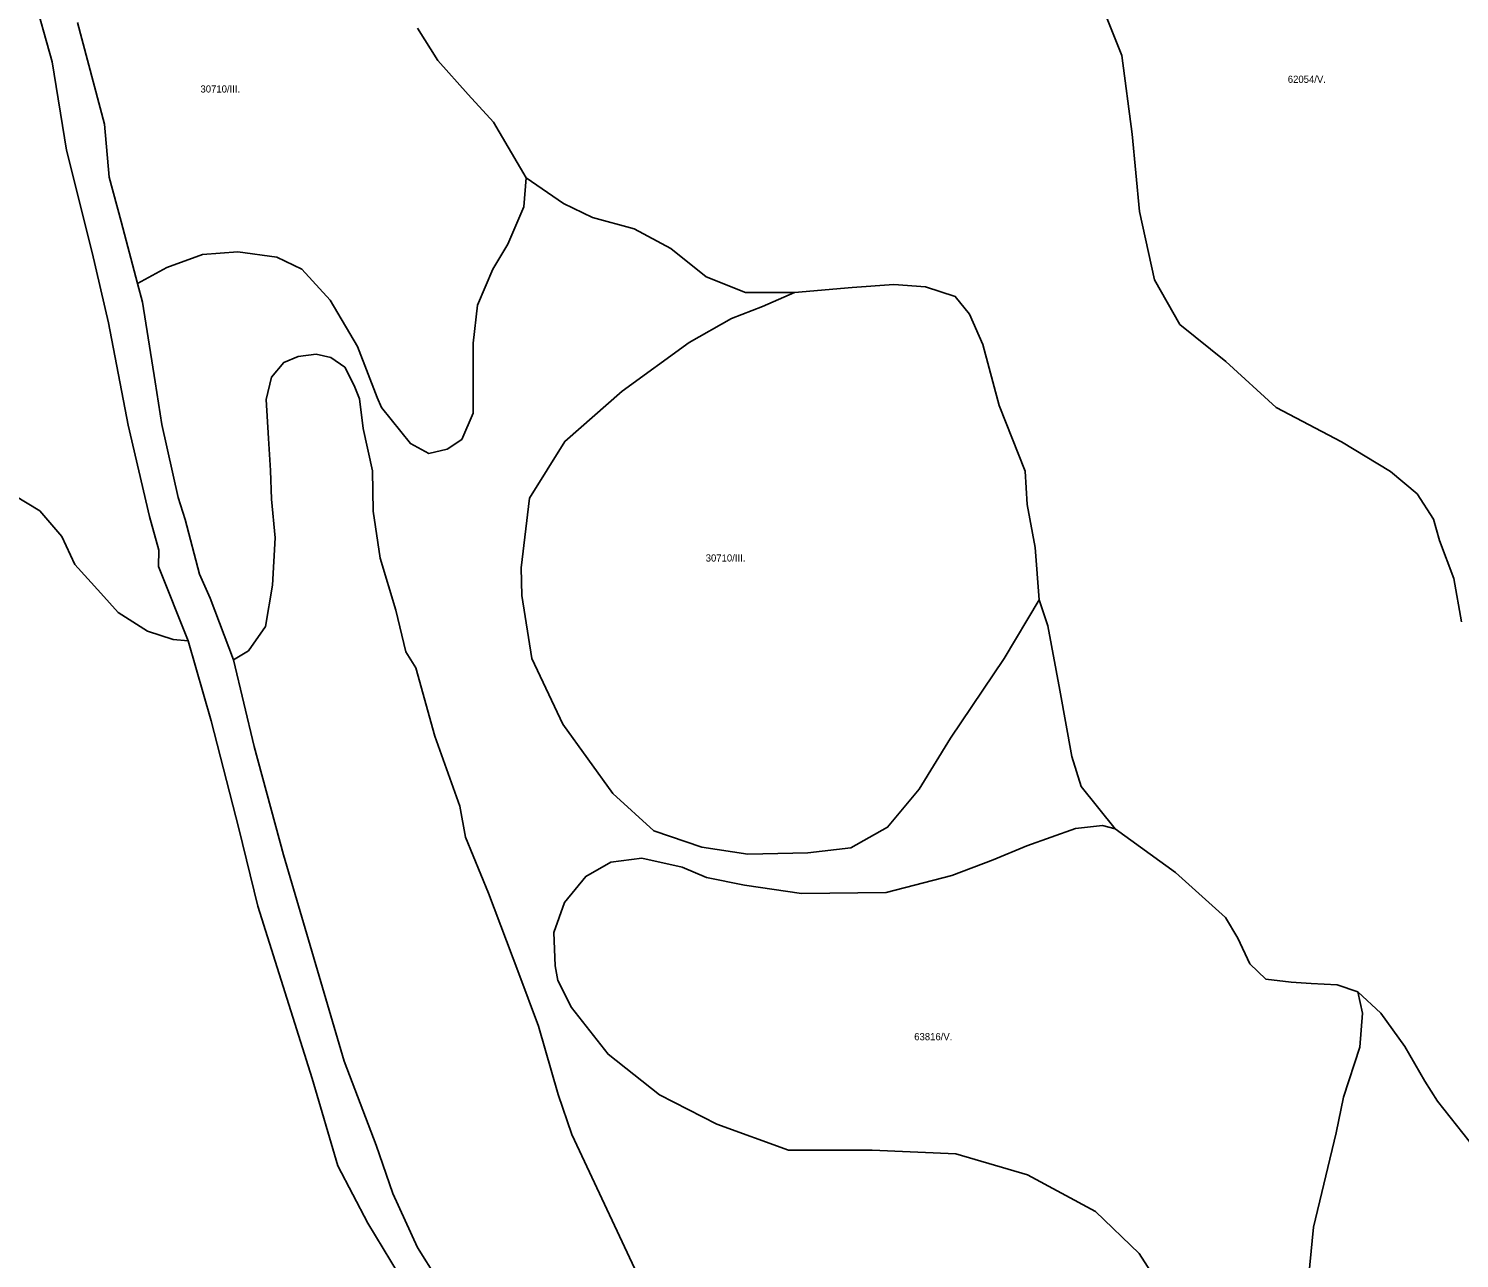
# Model space of a CAD drawing. Extents: x -521621 to -516761, y -1190184 to -1184927.
# Drawn here: x -519227 to -518423, y -1188783 to -1188092 of the extents above; entities that cross this region are included whole.
import ezdxf

# ---------------------------------------------------------------- set-up
doc = ezdxf.new("R2010")
doc.units = 0
doc.layers.add('BPEJ_s', color=7, linetype='Continuous')

msp = doc.modelspace()

# ---------------------------------------------------------------- linework, layer by layer
at = {"layer": 'BPEJ_s'}
for points in [[(-518422.16, -1188425.14), (-518426.52, -1188400.94), (-518434.45, -1188379.52), (-518437.78, -1188367.58), (-518446.95, -1188353.39), (-518461.97, -1188340.87), (-518489.49, -1188324.18), (-518526.18, -1188304.99), (-518554.54, -1188279.12), (-518580.39, -1188258.26), (-518594.57, -1188233.22), (-518602.91, -1188194.83), (-518607.08, -1188151.44), (-518612.92, -1188107.21), (-518629.6, -1188065.48)], [(-518629.6, -1188065.48), (-518612.92, -1188107.21), (-518607.08, -1188151.44), (-518602.91, -1188194.83), (-518594.57, -1188233.22), (-518580.39, -1188258.26), (-518554.54, -1188279.12), (-518526.18, -1188304.99), (-518489.49, -1188324.18), (-518461.97, -1188340.87), (-518446.95, -1188353.39), (-518437.78, -1188367.58), (-518434.45, -1188379.52), (-518426.52, -1188400.94), (-518422.16, -1188425.14)], [(-519224.72, -1188071.37), (-519213.76, -1188110.85), (-519205.61, -1188160.41), (-519191.21, -1188217.96), (-519182.06, -1188257.39), (-519170.92, -1188314.73), (-519158.98, -1188366.11), (-519153.68, -1188385.07), (-519153.92, -1188394.14), (-519137.31, -1188435.82), (-519145.71, -1188435.12), (-519160.09, -1188430.53), (-519176.55, -1188419.9), (-519186.35, -1188409.06), (-519200.93, -1188393), (-519208.23, -1188377.36), (-519220.53, -1188362.97), (-519234.9, -1188354.21)], [(-519014.92, -1188798.36), (-519036.31, -1188762.86), (-519053.26, -1188730.58), (-519067.71, -1188681.58), (-519098.18, -1188584.82), (-519108.75, -1188541.22), (-519124.4, -1188480.74), (-519137.31, -1188435.82), (-519153.92, -1188394.14), (-519153.68, -1188385.07), (-519158.98, -1188366.11), (-519170.92, -1188314.73), (-519182.06, -1188257.39), (-519191.21, -1188217.96), (-519205.61, -1188160.41), (-519213.76, -1188110.85), (-519224.72, -1188071.37)], [(-519008.55, -1188091.89), (-518997.05, -1188110.14), (-518980, -1188129.19), (-518965.73, -1188144.66), (-518947.49, -1188176), (-518948.68, -1188192.27), (-518957.8, -1188213.29), (-518966.12, -1188227.18), (-518974.85, -1188247.41), (-518977.23, -1188268.83), (-518977.23, -1188308.11), (-518983.57, -1188322.78), (-518991.9, -1188328.34), (-519002.2, -1188330.72), (-519012.51, -1188325.17), (-519023.22, -1188311.68), (-519028.77, -1188304.93), (-519031.1, -1188299.37), (-519042.15, -1188270.59), (-519057.57, -1188244.73), (-519073.4, -1188227.22), (-519087.58, -1188220.55), (-519109.46, -1188217.42), (-519129.25, -1188219.09), (-519149.26, -1188226.38), (-519165.74, -1188235.26), (-519174.9, -1188200.44), (-519181.72, -1188175.58), (-519184.34, -1188145.83), (-519199.49, -1188088.69)], [(-519199.49, -1188088.69), (-519184.34, -1188145.83), (-519181.72, -1188175.58), (-519174.9, -1188200.44), (-519165.74, -1188235.26), (-519162.96, -1188245.84), (-519155.8, -1188290.44), (-519152.02, -1188314.53), (-519142.86, -1188355.35), (-519138.89, -1188367.7), (-519130.84, -1188398.42), (-519124.86, -1188412.01), (-519111.79, -1188446.64), (-519100.17, -1188495.16), (-519083.81, -1188556.01), (-519049.7, -1188671.8), (-519031.72, -1188719.07), (-519022.31, -1188746.23), (-519008.42, -1188776.51), (-518997.38, -1188794.11)], [(-518417.8, -1188716.79), (-518435.53, -1188694.4), (-518442.78, -1188683.01), (-518453.88, -1188663.57), (-518467.36, -1188644.92), (-518480.44, -1188633.02), (-518491.94, -1188629.05), (-518506.61, -1188628.26), (-518517.71, -1188627.47), (-518531.98, -1188625.88), (-518541.1, -1188617.15), (-518547.84, -1188602.87), (-518554.6, -1188591.14), (-518582.81, -1188565.98), (-518616.68, -1188541.35), (-518635.69, -1188517.62), (-518641.01, -1188500.91), (-518647.75, -1188463.62), (-518654.49, -1188427.52), (-518659.25, -1188412.84), (-518661.63, -1188383.49), (-518665.99, -1188359.28), (-518667.18, -1188340.64), (-518681.85, -1188303.74), (-518690.97, -1188269.62), (-518698.5, -1188252.56), (-518706.43, -1188242.65), (-518723.09, -1188237.09), (-518740.93, -1188235.9), (-518764.32, -1188237.49), (-518796.83, -1188240.27), (-518824.19, -1188240.27), (-518846.39, -1188231.54), (-518866.21, -1188215.67), (-518886.83, -1188204.56), (-518910.22, -1188198.22), (-518926.48, -1188190.28), (-518947.49, -1188176), (-518965.73, -1188144.66), (-518980, -1188129.19), (-518997.05, -1188110.14), (-519008.55, -1188091.89)], [(-519165.74, -1188235.26), (-519149.26, -1188226.38), (-519129.25, -1188219.09), (-519109.46, -1188217.42), (-519087.58, -1188220.55), (-519073.4, -1188227.22), (-519057.57, -1188244.73), (-519042.15, -1188270.59), (-519031.1, -1188299.37), (-519028.77, -1188304.93), (-519023.22, -1188311.68), (-519012.51, -1188325.17), (-519002.2, -1188330.72), (-518991.9, -1188328.34), (-518983.57, -1188322.78), (-518977.23, -1188308.11), (-518977.23, -1188287.87), (-518977.23, -1188268.83), (-518974.85, -1188247.41), (-518966.12, -1188227.18), (-518957.8, -1188213.29), (-518948.68, -1188192.27), (-518947.49, -1188176)], [(-518947.49, -1188176), (-518926.48, -1188190.28), (-518910.22, -1188198.22), (-518886.83, -1188204.56), (-518866.21, -1188215.67), (-518846.39, -1188231.54), (-518824.19, -1188240.27), (-518796.83, -1188240.27)], [(-519111.79, -1188446.64), (-519124.86, -1188412.01), (-519130.84, -1188398.42), (-519138.89, -1188367.7), (-519142.86, -1188355.35), (-519152.02, -1188314.53), (-519155.8, -1188290.44), (-519162.96, -1188245.84), (-519165.74, -1188235.26)], [(-518796.83, -1188240.27), (-518814.67, -1188248.2), (-518832.12, -1188254.95), (-518855.9, -1188268.44), (-518893.57, -1188295.81), (-518925.68, -1188323.98), (-518945.51, -1188355.71), (-518950.26, -1188394.99), (-518949.87, -1188410.46), (-518944.32, -1188445.77), (-518926.87, -1188482.66), (-518898.72, -1188521.54), (-518875.73, -1188542.57), (-518848.77, -1188551.69), (-518823, -1188555.66), (-518789.29, -1188554.87), (-518765.11, -1188552.09), (-518744.49, -1188540.58), (-518726.65, -1188519.16), (-518709.21, -1188490.6), (-518679.07, -1188445.77), (-518659.25, -1188412.84)], [(-518997.38, -1188794.11), (-519008.42, -1188776.51), (-519022.31, -1188746.23), (-519031.72, -1188719.07), (-519049.7, -1188671.8), (-519083.81, -1188556.01), (-519100.17, -1188495.16), (-519111.79, -1188446.64), (-519103.41, -1188441.58), (-519093.82, -1188427.82), (-519089.86, -1188404.68), (-519088.4, -1188377.99), (-519090.49, -1188356.3), (-519091.12, -1188340.24), (-519092.16, -1188322.3), (-519093.41, -1188300.41), (-519090.49, -1188287.9), (-519083.62, -1188279.56), (-519075.49, -1188276.22), (-519065.49, -1188274.97), (-519057.15, -1188276.84), (-519049.23, -1188282.27), (-519044.02, -1188292.48), (-519041.11, -1188299.99), (-519039.02, -1188316.67), (-519033.81, -1188340.44), (-519033.39, -1188363.17), (-519029.44, -1188389.45), (-519020.68, -1188418.64), (-519015.06, -1188441.99), (-519009.43, -1188450.96), (-518998.8, -1188489.33), (-518984.63, -1188528.74), (-518981.51, -1188546.04), (-518968.59, -1188577.53), (-518951.5, -1188622.57), (-518940.46, -1188652.18), (-518929.41, -1188690.55), (-518921.73, -1188713.08), (-518879.59, -1188803.31)], [(-518879.59, -1188803.31), (-518921.73, -1188713.08), (-518929.41, -1188690.55), (-518940.46, -1188652.18), (-518951.5, -1188622.57), (-518968.59, -1188577.53), (-518981.51, -1188546.04), (-518984.63, -1188528.74), (-518998.8, -1188489.33), (-519009.43, -1188450.96), (-519015.06, -1188441.99), (-519020.68, -1188418.64), (-519029.44, -1188389.45), (-519033.39, -1188363.17), (-519033.81, -1188340.44), (-519039.02, -1188316.67), (-519041.11, -1188299.99), (-519044.02, -1188292.48), (-519049.23, -1188282.27), (-519057.15, -1188276.84), (-519065.49, -1188274.97), (-519075.49, -1188276.22), (-519083.62, -1188279.56), (-519090.49, -1188287.9), (-519093.41, -1188300.41), (-519092.16, -1188322.3), (-519091.12, -1188340.24), (-519090.49, -1188356.3), (-519088.4, -1188377.99), (-519089.86, -1188404.68), (-519093.82, -1188427.82), (-519103.41, -1188441.58), (-519111.79, -1188446.64)], [(-519234.9, -1188354.21), (-519220.53, -1188362.97), (-519208.23, -1188377.36), (-519200.93, -1188393), (-519186.35, -1188409.06), (-519176.55, -1188419.9), (-519160.09, -1188430.53), (-519145.71, -1188435.12), (-519137.31, -1188435.82), (-519124.4, -1188480.74), (-519108.75, -1188541.22), (-519098.18, -1188584.82), (-519067.71, -1188681.58), (-519053.26, -1188730.58), (-519036.31, -1188762.86), (-519014.92, -1188798.36)], [(-518659.25, -1188412.84), (-518654.49, -1188427.52), (-518647.75, -1188463.62), (-518641.01, -1188500.91), (-518635.69, -1188517.62), (-518616.68, -1188541.35)], [(-518587.52, -1188804.29), (-518603.21, -1188779.77), (-518627.71, -1188756.23), (-518665.93, -1188735.64), (-518706.11, -1188723.87), (-518753.16, -1188721.91), (-518800.2, -1188721.91), (-518840.38, -1188707.2), (-518872.52, -1188690.76), (-518901.49, -1188668.03), (-518921.91, -1188641.75), (-518929.62, -1188626.53), (-518931.08, -1188618.4), (-518931.91, -1188599.63), (-518925.87, -1188582.74), (-518913.99, -1188568.15), (-518899.82, -1188560.22), (-518882.52, -1188557.93), (-518859.81, -1188562.93), (-518846.26, -1188568.77), (-518824.8, -1188573.15), (-518792.91, -1188577.74), (-518745.19, -1188577.11), (-518708.3, -1188567.73), (-518685.17, -1188558.76), (-518666.21, -1188551.05), (-518638.91, -1188541.25), (-518623.7, -1188539.58), (-518616.68, -1188541.35), (-518582.81, -1188565.98), (-518554.6, -1188591.14), (-518547.84, -1188602.87), (-518541.1, -1188617.15), (-518531.98, -1188625.88), (-518517.71, -1188627.47), (-518506.61, -1188628.26), (-518491.94, -1188629.05), (-518480.44, -1188633.02), (-518477.66, -1188644.92), (-518479.25, -1188663.96), (-518488.37, -1188692.13), (-518492.46, -1188712.1), (-518505.2, -1188765.06), (-518510.1, -1188815.07)], [(-518616.68, -1188541.35), (-518623.7, -1188539.58), (-518638.91, -1188541.25), (-518666.21, -1188551.05), (-518685.17, -1188558.76), (-518708.3, -1188567.73), (-518745.19, -1188577.11), (-518792.91, -1188577.74), (-518824.8, -1188573.15), (-518846.26, -1188568.77), (-518859.81, -1188562.93), (-518882.52, -1188557.93), (-518899.82, -1188560.22), (-518913.99, -1188568.15), (-518925.87, -1188582.74), (-518931.91, -1188599.63), (-518931.08, -1188618.4), (-518929.62, -1188626.53), (-518921.91, -1188641.75), (-518901.49, -1188668.03), (-518872.52, -1188690.76), (-518840.38, -1188707.2), (-518800.2, -1188721.91), (-518753.16, -1188721.91), (-518706.11, -1188723.87), (-518665.93, -1188735.64), (-518627.71, -1188756.23), (-518603.21, -1188779.77), (-518587.52, -1188804.29)], [(-518400.33, -1189093.59), (-518428.75, -1189051.42), (-518460.11, -1188981.79), (-518473.83, -1188956.29), (-518489.52, -1188916.08), (-518503.24, -1188862.15), (-518510.1, -1188815.07), (-518505.2, -1188765.06), (-518492.46, -1188712.1), (-518488.37, -1188692.13), (-518479.25, -1188663.96), (-518477.66, -1188644.92), (-518480.44, -1188633.02)], [(-518480.44, -1188633.02), (-518467.36, -1188644.92), (-518453.88, -1188663.57), (-518442.78, -1188683.01), (-518435.53, -1188694.4), (-518417.8, -1188716.79), (-518378.87, -1188769.99)]]:
    msp.add_lwpolyline(points, dxfattribs=at)
msp.add_lwpolyline([(-518796.83, -1188240.27), (-518764.32, -1188237.49), (-518740.93, -1188235.9), (-518723.09, -1188237.09), (-518706.43, -1188242.65), (-518698.5, -1188252.56), (-518690.97, -1188269.62), (-518681.85, -1188303.74), (-518667.18, -1188340.64), (-518665.99, -1188359.28), (-518661.63, -1188383.49), (-518659.25, -1188412.84), (-518679.07, -1188445.77), (-518709.21, -1188490.6), (-518726.65, -1188519.16), (-518744.49, -1188540.58), (-518765.11, -1188552.09), (-518789.29, -1188554.87), (-518823, -1188555.66), (-518848.77, -1188551.69), (-518875.73, -1188542.57), (-518898.72, -1188521.54), (-518926.87, -1188482.66), (-518944.32, -1188445.77), (-518949.87, -1188410.46), (-518950.26, -1188394.99), (-518945.51, -1188355.71), (-518925.68, -1188323.98), (-518893.57, -1188295.81), (-518855.9, -1188268.44), (-518832.12, -1188254.95), (-518814.67, -1188248.2)], close=True, dxfattribs=at)

# ---------------------------------------------------------------- texts
for s, p in [('30710/III.', (-519130.38, -1188128.07)), ('62054/V.', (-518519.69, -1188122.63)), ('30710/III.', (-518846.62, -1188391.38)), ('63816/V.', (-518729.51, -1188660.12))]:
    msp.add_text(s, height=4, dxfattribs=at).set_placement(p)

doc.saveas('drawing.dxf')
